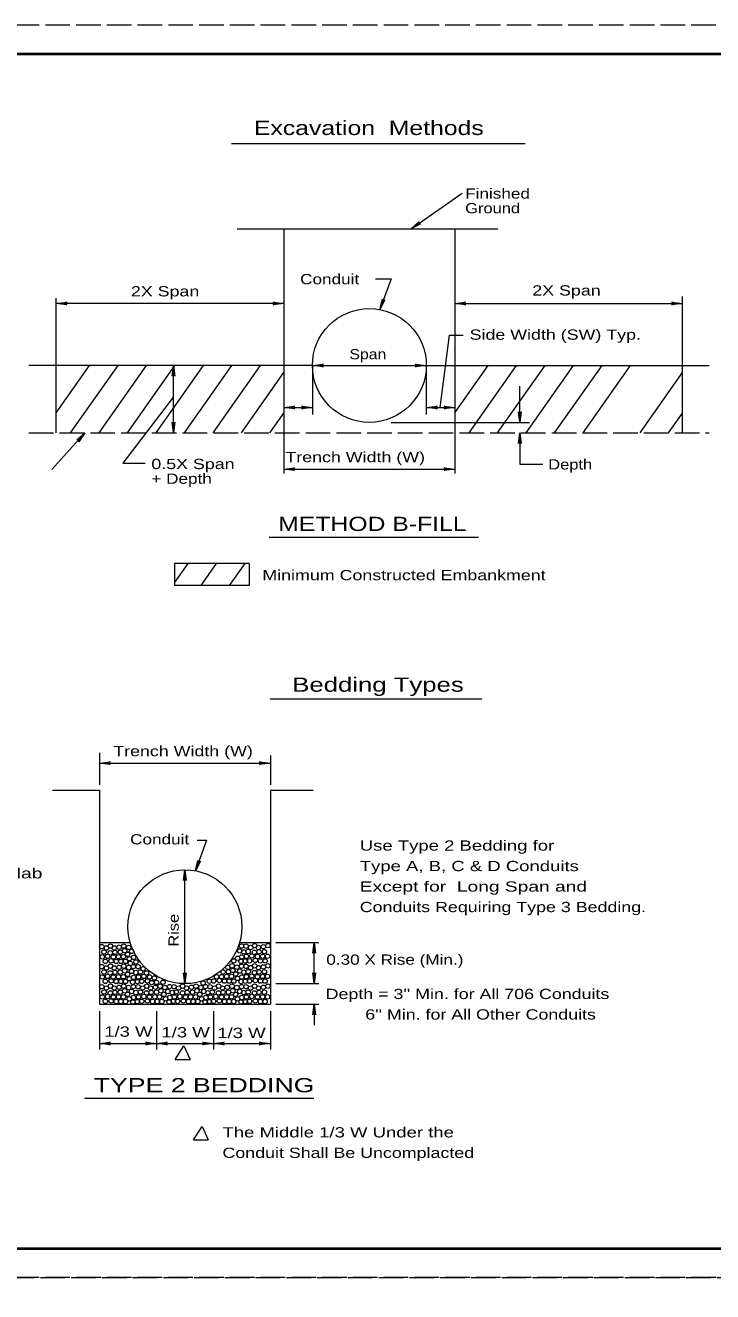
# Model space of a CAD drawing. Extents: x 750.7 to 784.7, y 834.8 to 878.8.
# Drawn here: x 761.19 to 773.25, y 856.53 to 878.78 of the extents above; entities that cross this region are included whole.
import ezdxf

# ---------------------------------------------------------------- set-up
doc = ezdxf.new("R2010")
doc.units = 0
doc.header["$LTSCALE"] = 0.072
doc.linetypes.add('LONG_DASHED', pattern=[7.5, 6, -1.5])
doc.layers.add('1', color=7, linetype='Continuous', lineweight=13)
doc.layers.add('47', color=7, linetype='Continuous', lineweight=13)

msp = doc.modelspace()

# ---------------------------------------------------------------- linework, layer by layer
at = {"layer": '1', "lineweight": 40}
msp.add_line((752.65083, 878.28433), (784.15083, 878.28433), dxfattribs=at)
at = {"layer": '1'}
for p, q in [((764.80592, 876.71083), (769.96108, 876.71083)), ((767.95875, 875.20608), (768.85525, 875.83333)), ((764.9045, 875.20608), (769.48042, 875.20608)), ((765.7275, 875.20608), (765.7275, 871.62283)), ((768.7275, 875.20608), (768.7275, 871.62283)), ((761.72992, 872.80642), (761.72992, 873.99033)), ((772.72508, 872.80642), (772.72508, 874.0215)), ((765.7275, 873.89675), (761.72992, 873.89675)), ((768.7275, 873.89675), (772.72508, 873.89675)), ((766.2275, 872.80642), (761.24933, 872.80642)), ((761.72992, 871.62283), (761.72992, 872.80642)), ((761.72992, 871.97475), (762.31475, 872.80642)), ((761.98242, 871.62283), (762.81475, 872.80642)), ((762.48242, 871.62283), (763.31475, 872.80642)), ((762.98242, 871.62283), (763.81475, 872.80642)), ((763.48242, 871.62283), (764.31475, 872.80642)), ((763.78933, 871.62283), (763.78933, 872.80642)), ((763.98242, 871.62283), (764.81475, 872.80642)), ((764.48242, 871.62283), (765.31475, 872.80642)), ((764.98242, 871.62283), (765.7275, 872.68233)), ((766.2275, 872.80817), (766.2275, 871.94717)), ((766.2275, 872.80817), (768.2275, 872.80817)), ((768.2275, 872.80817), (768.2275, 871.94717)), ((768.2275, 872.80642), (773.192, 872.80642)), ((768.7275, 871.97475), (769.31233, 872.80642)), ((768.98, 871.62283), (769.81233, 872.80642)), ((769.48, 871.62283), (770.31233, 872.80642)), ((769.98, 871.62283), (770.81233, 872.80642)), ((770.48, 871.62283), (771.31233, 872.80642)), ((770.98, 871.62283), (771.81233, 872.80642)), ((771.98, 871.62283), (772.72508, 872.68233)), ((772.72508, 871.62283), (772.72508, 872.80642)), ((769.86975, 871.80842), (769.86975, 872.44625)), ((765.7275, 872.07117), (766.2275, 872.07117)), ((768.2275, 872.07117), (768.7275, 872.07117)), ((765.48242, 871.62283), (765.7275, 871.97133)), ((767.60908, 871.80842), (770.04125, 871.80842)), ((772.48, 871.62283), (772.72508, 871.97133)), ((761.65467, 870.98025), (762.23158, 871.62283)), ((765.7275, 871.62283), (765.7275, 870.91083)), ((768.7275, 871.62283), (768.7275, 870.91083)), ((769.86975, 871.62283), (769.86975, 871.07375)), ((765.7275, 870.98883), (768.7275, 870.98883)), ((769.86975, 871.07375), (770.27517, 871.07375)), ((765.46683, 869.7935), (769.14342, 869.7935)), ((765.11458, 869.32842), (763.80492, 869.32842)), ((763.80492, 868.9865), (764.04533, 869.32842)), ((763.80492, 869.32842), (763.80492, 868.94108)), ((764.27292, 868.94108), (764.54533, 869.32842)), ((764.77292, 868.94108), (765.04533, 869.32842)), ((765.11458, 869.32842), (765.11458, 868.94108)), ((765.11458, 868.94108), (763.80492, 868.94108)), ((765.4885, 866.94983), (769.2005, 866.94983)), ((762.48892, 866.00217), (762.48892, 865.44067)), ((762.48892, 865.82275), (765.48892, 865.82275)), ((765.48892, 865.95367), (765.48892, 865.44067)), ((761.66592, 865.344), (762.48892, 865.344)), ((762.48892, 865.344), (762.48892, 861.58825)), ((765.48892, 865.344), (765.48892, 861.58825)), ((765.48892, 865.344), (766.24183, 865.344)), ((763.98892, 861.94608), (763.98892, 863.94608)), ((762.48892, 862.66883), (763.02808, 862.66883)), ((764.94975, 862.66883), (765.48892, 862.66883)), ((765.58517, 862.66883), (766.3415, 862.66883)), ((766.25875, 861.94608), (766.25875, 862.66883)), ((765.58517, 861.94608), (766.3415, 861.94608)), ((762.48892, 861.58825), (765.48892, 861.58825)), ((765.58517, 861.58825), (766.3415, 861.58825)), ((766.25875, 861.58825), (766.25875, 861.21483)), ((762.48892, 861.46308), (762.48892, 860.78925)), ((763.48892, 861.46308), (763.48892, 860.78925)), ((764.48892, 861.46308), (764.48892, 860.78925)), ((765.48892, 861.46308), (765.48892, 860.78925)), ((763.81858, 860.61525), (764.0785, 860.61525)), ((762.22825, 859.93142), (766.25475, 859.93142)), ((764.14025, 859.20008), (764.40017, 859.20008))]:
    msp.add_line(p, q, dxfattribs=at)
at = {"layer": '1', "linetype": 'LONG_DASHED'}
msp.add_line((761.24933, 871.62283), (773.192, 871.62283), dxfattribs=at)
at = {"layer": '1', "lineweight": 25}
msp.add_line((784.15083, 857.28433), (752.65083, 857.28433), dxfattribs=at)
at = {"layer": '1', "linetype": 'LONG_DASHED'}
for points in [[(750.65083, 856.78433), (784.65083, 856.78433), (784.65083, 878.78433), (750.65083, 878.78433)], [(750.65083, 834.78433), (784.65083, 834.78433), (784.65083, 856.78433), (750.65083, 856.78433)]]:
    msp.add_lwpolyline(points, close=True, dxfattribs=at)
at = {"layer": '1', "lineweight": 40}
for points in [[(784.15083, 857.28433), (752.65083, 857.28433), (752.65083, 878.28433), (784.15083, 878.28433)], [(784.15083, 857.28433), (752.65083, 857.28433), (752.65083, 878.28433)]]:
    msp.add_lwpolyline(points, dxfattribs=at)
at = {"layer": '1'}
for points in [[(767.33508, 874.32825), (767.60792, 874.32825), (767.41358, 873.79067)], [(768.47325, 872.07117), (768.637, 873.33783), (768.872, 873.33783)], [(763.78933, 872.25908), (762.90058, 871.08933), (763.29042, 871.08933)], [(764.20558, 864.46617), (764.36933, 864.46617), (764.175, 863.92858)], [(762.48892, 860.89567), (763.48892, 860.89567), (764.48892, 860.89567), (765.48892, 860.89567)], [(763.81858, 860.61525), (763.97217, 860.85175), (764.0785, 860.61525)], [(764.14025, 859.20008), (764.29383, 859.43658), (764.40017, 859.20008)]]:
    msp.add_lwpolyline(points, dxfattribs=at)
for centre, radius in [((767.2275, 872.80817), 1), ((763.98892, 862.94608), 1), ((762.52958, 862.59625), 0.03892), ((762.68163, 862.60606), 0.03892), ((762.91555, 862.60606), 0.03892), ((764.98305, 862.60706), 0.03892), ((765.061, 862.60508), 0.03892), ((765.21305, 862.6149), 0.03892), ((765.36513, 862.5954), 0.03892), ((765.44697, 862.6149), 0.03892), ((762.53738, 862.4169), 0.03892), ((762.56855, 862.50265), 0.03892), ((762.61136, 862.57283), 0.03892), ((762.63088, 862.42465), 0.03892), ((762.67772, 862.48706), 0.03892), ((762.7323, 862.41498), 0.03892), ((762.74788, 862.57281), 0.03892), ((762.75963, 862.4969), 0.03892), ((762.82197, 862.4189), 0.03892), ((762.83372, 862.58656), 0.03892), ((762.85313, 862.50073), 0.03892), ((762.90772, 862.4189), 0.03892), ((762.93113, 862.52415), 0.03892), ((762.9818, 862.46173), 0.03892), ((763.0013, 862.58265), 0.03892), ((763.01297, 862.38381), 0.03892), ((763.05197, 862.51248), 0.03892), ((763.08705, 862.40715), 0.03892), ((764.91288, 862.39265), 0.03892), ((764.95188, 862.52131), 0.03892), ((764.98697, 862.41598), 0.03892), ((764.98705, 862.41598), 0.03892), ((764.98705, 862.41598), 0.03892), ((765.02198, 862.50364), 0.03892), ((765.0688, 862.42573), 0.03892), ((765.09997, 862.51148), 0.03892), ((765.14278, 862.58166), 0.03892), ((765.1623, 862.43348), 0.03892), ((765.20913, 862.4959), 0.03892), ((765.26372, 862.42381), 0.03892), ((765.2793, 862.58165), 0.03892), ((765.29105, 862.50573), 0.03892), ((765.35338, 862.42773), 0.03892), ((765.38455, 862.50956), 0.03892), ((765.43913, 862.42773), 0.03892), ((762.52958, 862.2445), 0.03892), ((762.56855, 862.1509), 0.03892), ((762.59197, 862.3389), 0.03892), ((762.61136, 862.22108), 0.03892), ((762.68163, 862.25431), 0.03892), ((762.6933, 862.34673), 0.03892), ((762.74788, 862.22106), 0.03892), ((762.78297, 862.33698), 0.03892), ((762.83372, 862.23481), 0.03892), ((762.85313, 862.14898), 0.03892), ((762.86488, 862.33698), 0.03892), ((762.91555, 862.25431), 0.03892), ((762.93113, 862.1724), 0.03892), ((762.94672, 862.33698), 0.03892), ((763.0013, 862.2309), 0.03892), ((763.02962, 862.30263), 0.03892), ((763.05197, 862.16073), 0.03892), ((763.08313, 862.24648), 0.03892), ((763.12842, 862.32612), 0.03892), ((763.16667, 862.2445), 0.03892), ((763.20563, 862.1509), 0.03892), ((763.25432, 862.20632), 0.03892), ((764.65955, 862.15106), 0.03892), ((764.74248, 862.23185), 0.03892), ((764.75305, 862.1549), 0.03892), ((764.81547, 862.26023), 0.03892), ((764.83105, 862.17831), 0.03892), ((764.84663, 862.34581), 0.03892), ((764.90122, 862.23681), 0.03892), ((764.95188, 862.16665), 0.03892), ((764.97522, 862.33806), 0.03892), ((764.98305, 862.2524), 0.03892), ((765.02198, 862.14898), 0.03892), ((765.04931, 862.34381), 0.03892), ((765.061, 862.25042), 0.03892), ((765.09997, 862.15681), 0.03892), ((765.12338, 862.34773), 0.03892), ((765.14278, 862.22699), 0.03892), ((765.21305, 862.26023), 0.03892), ((765.22472, 862.35556), 0.03892), ((765.2793, 862.22698), 0.03892), ((765.29105, 862.15106), 0.03892), ((765.31438, 862.34581), 0.03892), ((765.36513, 862.24073), 0.03892), ((765.38455, 862.1549), 0.03892), ((765.3963, 862.34581), 0.03892), ((765.44697, 862.26023), 0.03892), ((762.53738, 862.06515), 0.03892), ((762.59197, 861.98715), 0.03892), ((762.63088, 862.0729), 0.03892), ((762.67772, 862.13531), 0.03892), ((762.6933, 861.99498), 0.03892), ((762.7323, 862.06323), 0.03892), ((762.75963, 862.14515), 0.03892), ((762.78297, 861.98523), 0.03892), ((762.82197, 862.06715), 0.03892), ((762.86488, 861.98523), 0.03892), ((762.90772, 862.06715), 0.03892), ((762.94672, 861.98523), 0.03892), ((762.9818, 862.10998), 0.03892), ((763.01297, 862.03206), 0.03892), ((763.07204, 861.97255), 0.03892), ((763.08705, 862.0554), 0.03892), ((763.12764, 862.14306), 0.03892), ((763.15498, 861.98323), 0.03892), ((763.17447, 862.06515), 0.03892), ((763.22905, 861.98715), 0.03892), ((763.26797, 862.0729), 0.03892), ((763.3148, 862.13531), 0.03892), ((763.33038, 861.99498), 0.03892), ((763.36938, 862.06323), 0.03892), ((763.40528, 861.96457), 0.03892), ((763.45212, 862.04546), 0.03892), ((763.49013, 861.96749), 0.03892), ((763.60446, 861.97042), 0.03892), ((764.30833, 861.95676), 0.03892), ((764.41781, 861.98914), 0.03892), ((764.49188, 861.99306), 0.03892), ((764.5456, 862.06697), 0.03892), ((764.59322, 862.0009), 0.03892), ((764.63222, 862.06915), 0.03892), ((764.68288, 861.99115), 0.03892), ((764.72188, 862.07306), 0.03892), ((764.7648, 861.99115), 0.03892), ((764.80763, 862.07306), 0.03892), ((764.84663, 861.99115), 0.03892), ((764.88172, 862.1159), 0.03892), ((764.91288, 862.03798), 0.03892), ((764.97522, 861.9834), 0.03892), ((764.98697, 862.06131), 0.03892), ((764.98705, 862.06131), 0.03892), ((764.98705, 862.06131), 0.03892), ((765.04931, 861.98914), 0.03892), ((765.0688, 862.07106), 0.03892), ((765.12338, 861.99306), 0.03892), ((765.1623, 862.07881), 0.03892), ((765.20913, 862.14123), 0.03892), ((765.22472, 862.0009), 0.03892), ((765.26372, 862.06915), 0.03892), ((765.31438, 861.99115), 0.03892), ((765.35338, 862.07306), 0.03892), ((765.3963, 861.99115), 0.03892), ((765.43913, 862.07306), 0.03892), ((762.52958, 861.89242), 0.03892), ((762.53738, 861.71306), 0.03892), ((762.56855, 861.79881), 0.03892), ((762.61136, 861.86899), 0.03892), ((762.63088, 861.72081), 0.03892), ((762.67772, 861.78323), 0.03892), ((762.68163, 861.90223), 0.03892), ((762.7323, 861.71115), 0.03892), ((762.74788, 861.86898), 0.03892), ((762.75963, 861.79306), 0.03892), ((762.82197, 861.71506), 0.03892), ((762.83372, 861.88273), 0.03892), ((762.85313, 861.7969), 0.03892), ((762.90772, 861.71506), 0.03892), ((762.91555, 861.90223), 0.03892), ((762.93113, 861.82031), 0.03892), ((762.9818, 861.7579), 0.03892), ((763.0013, 861.87881), 0.03892), ((763.05197, 861.80865), 0.03892), ((763.08313, 861.8944), 0.03892), ((763.12764, 861.79098), 0.03892), ((763.16667, 861.89242), 0.03892), ((763.17447, 861.71306), 0.03892), ((763.20563, 861.79881), 0.03892), ((763.24844, 861.86899), 0.03892), ((763.26797, 861.72081), 0.03892), ((763.3148, 861.78323), 0.03892), ((763.31872, 861.90223), 0.03892), ((763.36938, 861.71115), 0.03892), ((763.38497, 861.86898), 0.03892), ((763.39672, 861.79306), 0.03892), ((763.45905, 861.71506), 0.03892), ((763.4708, 861.88273), 0.03892), ((763.49022, 861.7969), 0.03892), ((763.5448, 861.71506), 0.03892), ((763.55263, 861.90223), 0.03892), ((763.56822, 861.82031), 0.03892), ((763.61888, 861.7579), 0.03892), ((763.63838, 861.87881), 0.03892), ((763.68905, 861.80865), 0.03892), ((763.72022, 861.8944), 0.03892), ((763.76689, 861.79098), 0.03892), ((763.79808, 861.89242), 0.03892), ((763.80588, 861.71306), 0.03892), ((763.83705, 861.79881), 0.03892), ((763.87986, 861.86899), 0.03892), ((763.89938, 861.72081), 0.03892), ((763.94622, 861.78323), 0.03892), ((763.95013, 861.90223), 0.03892), ((764.0008, 861.71115), 0.03892), ((764.01638, 861.86898), 0.03892), ((764.02813, 861.79306), 0.03892), ((764.09047, 861.71506), 0.03892), ((764.10222, 861.88273), 0.03892), ((764.12163, 861.7969), 0.03892), ((764.17622, 861.71506), 0.03892), ((764.18405, 861.90223), 0.03892), ((764.19963, 861.82031), 0.03892), ((764.2503, 861.7579), 0.03892), ((764.2698, 861.87881), 0.03892), ((764.32047, 861.80865), 0.03892), ((764.35163, 861.8944), 0.03892), ((764.39056, 861.78714), 0.03892), ((764.4295, 861.89242), 0.03892), ((764.4373, 861.71306), 0.03892), ((764.46847, 861.79881), 0.03892), ((764.51128, 861.86899), 0.03892), ((764.5308, 861.72081), 0.03892), ((764.57763, 861.78323), 0.03892), ((764.58155, 861.90223), 0.03892), ((764.63222, 861.71115), 0.03892), ((764.6478, 861.86898), 0.03892), ((764.65955, 861.79306), 0.03892), ((764.72188, 861.71506), 0.03892), ((764.73363, 861.88273), 0.03892), ((764.75305, 861.7969), 0.03892), ((764.80763, 861.71506), 0.03892), ((764.81547, 861.90223), 0.03892), ((764.83105, 861.82031), 0.03892), ((764.88172, 861.7579), 0.03892), ((764.90122, 861.87881), 0.03892), ((764.95188, 861.80865), 0.03892), ((764.98305, 861.8944), 0.03892), ((765.02198, 861.79098), 0.03892), ((765.061, 861.89242), 0.03892), ((765.0688, 861.71306), 0.03892), ((765.09997, 861.79881), 0.03892), ((765.14278, 861.86899), 0.03892), ((765.1623, 861.72081), 0.03892), ((765.20913, 861.78323), 0.03892), ((765.21305, 861.90223), 0.03892), ((765.26372, 861.71115), 0.03892), ((765.2793, 861.86898), 0.03892), ((765.29105, 861.79306), 0.03892), ((765.35338, 861.71506), 0.03892), ((765.36513, 861.88273), 0.03892), ((765.38455, 861.7969), 0.03892), ((765.43913, 861.71506), 0.03892), ((765.44697, 861.90223), 0.03892), ((762.59197, 861.63506), 0.03892), ((762.6933, 861.6429), 0.03892), ((762.78297, 861.63315), 0.03892), ((762.86488, 861.63315), 0.03892), ((762.94672, 861.63315), 0.03892), ((763.01297, 861.67998), 0.03892), ((763.0753, 861.6254), 0.03892), ((763.08705, 861.70331), 0.03892), ((763.15498, 861.63114), 0.03892), ((763.22905, 861.63506), 0.03892), ((763.33038, 861.6429), 0.03892), ((763.42005, 861.63315), 0.03892), ((763.50197, 861.63315), 0.03892), ((763.5838, 861.63315), 0.03892), ((763.65005, 861.67998), 0.03892), ((763.71238, 861.6254), 0.03892), ((763.72413, 861.70331), 0.03892), ((763.78639, 861.63506), 0.03892), ((763.86047, 861.63506), 0.03892), ((763.9618, 861.6429), 0.03892), ((764.05147, 861.63315), 0.03892), ((764.13338, 861.63315), 0.03892), ((764.21522, 861.63315), 0.03892), ((764.28147, 861.67998), 0.03892), ((764.3438, 861.6254), 0.03892), ((764.35555, 861.70331), 0.03892), ((764.35555, 861.70331), 0.03892), ((764.41781, 861.63114), 0.03892), ((764.49188, 861.63506), 0.03892), ((764.59322, 861.6429), 0.03892), ((764.68288, 861.63315), 0.03892), ((764.7648, 861.63315), 0.03892), ((764.84663, 861.63315), 0.03892), ((764.91288, 861.67998), 0.03892), ((764.97522, 861.6254), 0.03892), ((764.98697, 861.70331), 0.03892), ((764.98705, 861.70331), 0.03892), ((764.98705, 861.70331), 0.03892), ((765.04931, 861.63114), 0.03892), ((765.12338, 861.63506), 0.03892), ((765.22472, 861.6429), 0.03892), ((765.31438, 861.63315), 0.03892), ((765.3963, 861.63315), 0.03892)]:
    msp.add_circle(centre, radius, dxfattribs=at)
at = {"layer": '47'}
for points in [[(768.12583, 875.29442), (767.95875, 875.20608), (768.09892, 875.33275)], [(761.91742, 873.87333), (761.72992, 873.89675), (761.91742, 873.92017)], [(765.54, 873.92017), (765.7275, 873.89675), (765.54, 873.87333)], [(767.49933, 873.959), (767.41358, 873.79067), (767.45533, 873.975)], [(768.915, 873.87333), (768.7275, 873.89675), (768.915, 873.92017)], [(772.53758, 873.92017), (772.72508, 873.89675), (772.53758, 873.87333)], [(763.76592, 872.61892), (763.78933, 872.80642), (763.81275, 872.61892)], [(766.415, 872.78475), (766.2275, 872.80817), (766.415, 872.83158)], [(768.04, 872.83158), (768.2275, 872.80817), (768.04, 872.78475)], [(765.915, 872.04775), (765.7275, 872.07117), (765.915, 872.09458)], [(766.04, 872.09458), (766.2275, 872.07117), (766.04, 872.04775)], [(768.415, 872.04775), (768.2275, 872.07117), (768.415, 872.09458)], [(768.54, 872.09458), (768.7275, 872.07117), (768.54, 872.04775)], [(769.89317, 871.99592), (769.86975, 871.80842), (769.84633, 871.99592)], [(763.81275, 871.81033), (763.78933, 871.62283), (763.76592, 871.81033)], [(762.08892, 871.49892), (762.23158, 871.62283), (762.12375, 871.46767)], [(769.84633, 871.43533), (769.86975, 871.62283), (769.89317, 871.43533)], [(765.915, 870.96542), (765.7275, 870.98883), (765.915, 871.01225)], [(768.54, 871.01225), (768.7275, 870.98883), (768.54, 870.96542)], [(762.67642, 865.79933), (762.48892, 865.82275), (762.67642, 865.84617)], [(765.30142, 865.84617), (765.48892, 865.82275), (765.30142, 865.79933)], [(764.26075, 864.09692), (764.175, 863.92858), (764.21675, 864.11292)], [(763.9655, 863.75858), (763.98892, 863.94608), (764.01233, 863.75858)], [(766.23533, 862.48133), (766.25875, 862.66883), (766.28217, 862.48133)], [(764.01233, 862.13358), (763.98892, 861.94608), (763.9655, 862.13358)], [(766.28217, 862.13358), (766.25875, 861.94608), (766.23533, 862.13358)], [(766.23533, 861.40075), (766.25875, 861.58825), (766.28217, 861.40075)], [(762.67642, 860.87225), (762.48892, 860.89567), (762.67642, 860.91908)], [(763.30142, 860.91908), (763.48892, 860.89567), (763.30142, 860.87225)], [(763.67642, 860.87225), (763.48892, 860.89567), (763.67642, 860.91908)], [(764.30142, 860.91908), (764.48892, 860.89567), (764.30142, 860.87225)], [(764.67642, 860.87225), (764.48892, 860.89567), (764.67642, 860.91908)], [(765.30142, 860.91908), (765.48892, 860.89567), (765.30142, 860.87225)]]:
    msp.add_lwpolyline(points, dxfattribs=at)
for centre, start, end in [((768.11238, 875.31358), 124.97915, 304.97915), ((761.91742, 873.89676), 90, 270), ((765.53999, 873.89674), 270, 90), ((767.47732, 873.96701), 160.12536, 340.12536), ((768.91501, 873.89676), 90, 270), ((772.53758, 873.89674), 270, 90), ((766.41501, 872.80817), 90, 270), ((768.03999, 872.80816), 270, 90), ((763.78934, 872.61891), 0, 180), ((765.91501, 872.07117), 90, 270), ((766.03999, 872.07116), 270, 90), ((768.41501, 872.07117), 90, 270), ((768.53999, 872.07116), 270, 90), ((769.86974, 871.99592), 180, 0), ((763.78933, 871.81034), 180, 0), ((762.10632, 871.4833), 318.08224, 138.08224), ((769.86976, 871.43533), 0, 180), ((765.91501, 870.98884), 90, 270), ((768.53999, 870.98883), 270, 90), ((762.67642, 865.82276), 90, 270), ((765.30141, 865.82274), 270, 90), ((764.23874, 864.10492), 160.12536, 340.12536), ((763.98892, 863.75858), 0, 180), ((766.25876, 862.48133), 0, 180), ((763.98891, 862.13359), 180, 0), ((766.25874, 862.13359), 180, 0), ((766.25876, 861.40074), 0, 180), ((762.67642, 860.89567), 90, 270), ((763.30141, 860.89566), 270, 90), ((763.67642, 860.89567), 90, 270), ((764.30141, 860.89566), 270, 90), ((764.67642, 860.89567), 90, 270), ((765.30141, 860.89566), 270, 90)]:
    msp.add_arc(centre, 0.02342, start, end, dxfattribs=at)

# ---------------------------------------------------------------- texts
at = {"layer": '1'}
for s, height, width, p in [('Excavation  Methods', 0.25, 1.3, (765.20075, 876.85692)), ('Finished', 0.18, 1.25, (768.90983, 875.73908)), ('Ground', 0.18, 1.2, (768.90983, 875.48108)), ('2X Span', 0.18, 1.3, (763.04092, 874.0215)), ('Conduit', 0.18, 1.25, (766.01217, 874.23467)), ('2X Span', 0.18, 1.3, (770.08808, 874.03708)), ('Side Width (SW) Typ.', 0.18, 1.3, (768.98767, 873.25983)), ('Span', 0.18, 1.15, (766.8775, 872.91667)), ('0.5X Span', 0.18, 1.3, (763.3995, 870.98733)), ('Trench Width (W)', 0.18, 1.3, (765.75308, 871.10875)), ('Depth', 0.18, 1.2, (770.36867, 870.98017)), ('+ Depth', 0.18, 1.25, (763.3995, 870.72933)), ('METHOD B-FILL', 0.25, 1.3, (765.62625, 869.89983)), ('Minimum Constructed Embankment', 0.18, 1.3, (765.3485, 869.03458)), ('Bedding Types', 0.25, 1.35, (765.87342, 867.07533)), ('Trench Width (W)', 0.18, 1.3, (762.73083, 865.94267)), ('Conduit', 0.18, 1.25, (763.02708, 864.393)), ('Use Type 2 Bedding for', 0.18, 1.35, (767.059, 864.28333)), ('and 706.052 on Slab ', 0.18, 1.4, (758.37692, 863.79567)), ('Type A, B, C & D Conduits ', 0.18, 1.35, (767.059, 863.92333)), ('Except for  Long Span and ', 0.18, 1.4, (767.059, 863.56333)), ('Conduits Requiring Type 3 Bedding.', 0.18, 1.3, (767.059, 863.20333)), ('0.30 X Rise (Min.)', 0.18, 1.25, (766.47142, 862.27875)), ("Depth = 3'' Min. for All 706 Conduits", 0.18, 1.3, (766.45967, 861.67583)), ("        6'' Min. for All Other Conduits", 0.18, 1.3, (766.45967, 861.31583)), ('1/3 W', 0.18, 1.35, (762.57183, 861.01383)), ('1/3 W', 0.18, 1.35, (763.57633, 861.00208)), ('1/3 W', 0.18, 1.35, (764.55708, 860.99025)), ('TYPE 2 BEDDING ', 0.25, 1.4, (762.38767, 860.03775)), ('The Middle 1/3 W Under the', 0.18, 1.35, (764.64833, 859.24467)), ('Conduit Shall Be Uncomplacted', 0.18, 1.3, (764.64833, 858.88467))]:
    msp.add_text(s, height=height, dxfattribs=dict(at, width=width)).set_placement(p)
at = {"layer": '1', "width": 1.2}
msp.add_text('Rise', height=0.18, rotation=90, dxfattribs=at).set_placement((763.88042, 862.59608))

doc.saveas('drawing.dxf')
